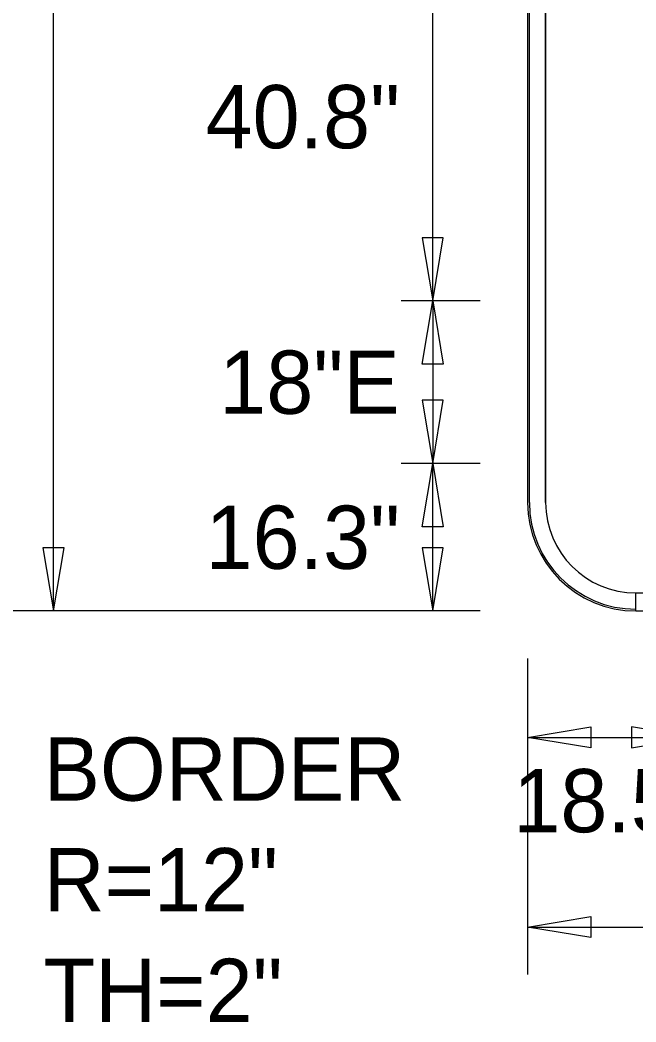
# Model space of a CAD drawing. Extents: x 2149934 to 2150188, y 145114 to 145238.
# Drawn here: x 2150026.84 to 2150032.52, y 145140.59 to 145149.83 of the extents above; entities that cross this region are included whole.
import ezdxf

# ---------------------------------------------------------------- set-up
doc = ezdxf.new("R2010")
doc.units = 0
for name, color, linetype in [('GSBWFILL', 7, 'Continuous'), ('GSCOLORFILL', 7, 'Continuous'), ('GSDIMS', 7, 'Continuous'), ('GSOUTLINE', 7, 'Continuous')]:
    doc.layers.add(name, color=color, linetype=linetype)

msp = doc.modelspace()

# ---------------------------------------------------------------- linework, layer by layer
at = {"layer": 'GSBWFILL'}
for p, q in [((2150031.5199, 145156.3826), (2150031.5199, 145145.3826)), ((2150031.6865, 145145.3826), (2150031.6865, 145156.3826)), ((2150032.5199, 145144.3826), (2150032.5199, 145144.5493))]:
    msp.add_line(p, q, dxfattribs=at)
for radius in [1, 0.8333]:
    msp.add_arc((2150032.5199, 145145.3826), radius, 180, 270, dxfattribs=at)
at = {"layer": 'GSCOLORFILL'}
for p, q in [((2150031.5199, 145156.3826), (2150031.5199, 145145.3826)), ((2150031.5199, 145156.3826), (2150031.5199, 145145.3826)), ((2150031.5199, 145156.3826), (2150031.5199, 145145.3826)), ((2150031.5365, 145145.3826), (2150031.5365, 145156.3826)), ((2150031.6865, 145145.3826), (2150031.6865, 145156.3826)), ((2150032.5199, 145144.3826), (2150032.5199, 145144.5493)), ((2150032.5199, 145144.3826), (2150032.5199, 145144.3993)), ((2150032.5199, 145144.3826), (2150046.0199, 145144.3826))]:
    msp.add_line(p, q, dxfattribs=at)
for radius in [1, 1, 1, 0.9833, 0.8333]:
    msp.add_arc((2150032.5199, 145145.3826), radius, 180, 270, dxfattribs=at)
at = {"layer": 'GSDIMS'}
for p, q in [((2150027.1448, 145144.3826), (2150027.1448, 145154.5852)), ((2150030.6448, 145147.2435), (2150030.6448, 145150.6434)), ((2150031.0823, 145147.2435), (2150030.3531, 145147.2435)), ((2150031.0823, 145147.2435), (2150030.3531, 145147.2435)), ((2150030.6448, 145147.2435), (2150030.6448, 145145.7435)), ((2150031.0823, 145145.7435), (2150030.3531, 145145.7435)), ((2150031.0823, 145145.7435), (2150030.3531, 145145.7435)), ((2150030.6448, 145144.3826), (2150030.6448, 145145.7435)), ((2150031.0823, 145144.3826), (2150024.0823, 145144.3826)), ((2150027.5823, 145144.3826), (2150026.8531, 145144.3826)), ((2150031.0823, 145144.3826), (2150030.3531, 145144.3826)), ((2150031.5198, 145143.9451), (2150031.5198, 145141.0284)), ((2150031.5198, 145143.6534), (2150031.5198, 145142.9243)), ((2150031.5198, 145143.2159), (2150033.0614, 145143.2159)), ((2150031.5198, 145141.9034), (2150031.5198, 145141.1743)), ((2150031.5198, 145141.4659), (2150047.0199, 145141.4659))]:
    msp.add_line(p, q, dxfattribs=at)
for points in [[(2150030.6448, 145147.2435), (2150030.742, 145147.8268), (2150030.5476, 145147.8268)], [(2150030.6448, 145147.2435), (2150030.742, 145146.6601), (2150030.5476, 145146.6601)], [(2150030.6448, 145145.7435), (2150030.742, 145146.3268), (2150030.5476, 145146.3268)], [(2150030.6448, 145145.7435), (2150030.742, 145145.1601), (2150030.5476, 145145.1601)], [(2150027.1448, 145144.3826), (2150027.242, 145144.9659), (2150027.0476, 145144.9659)], [(2150030.6448, 145144.3826), (2150030.742, 145144.9659), (2150030.5476, 145144.9659)], [(2150031.5198, 145143.2159), (2150032.1031, 145143.3132), (2150032.1031, 145143.1187)], [(2150033.0614, 145143.2159), (2150032.4781, 145143.3132), (2150032.4781, 145143.1187)], [(2150031.5198, 145141.4659), (2150032.1031, 145141.5632), (2150032.1031, 145141.3687)]]:
    msp.add_lwpolyline(points, close=True, dxfattribs=at)
at = {"layer": 'GSOUTLINE'}
for p, q in [((2150031.5199, 145156.3826), (2150031.5199, 145145.3826)), ((2150031.6865, 145156.3826), (2150031.6865, 145145.3826)), ((2150032.5199, 145144.5493), (2150046.0199, 145144.5493)), ((2150032.5199, 145144.3826), (2150046.0199, 145144.3826))]:
    msp.add_line(p, q, dxfattribs=at)
for radius in [1, 0.8333]:
    msp.add_arc((2150032.5199, 145145.3826), radius, 180, 270, dxfattribs=at)

# ---------------------------------------------------------------- texts
at = {"layer": 'GSDIMS'}
for s, p in [('40.8"', (2150028.5484, 145148.6517)), ('18"E', (2150028.6748, 145146.2018)), ('16.3"', (2150028.5484, 145144.7713)), ('BORDER', (2150027.0537, 145142.6326)), ('18.5"', (2150031.3883, 145142.3409)), ('R=12"', (2150027.0537, 145141.6118)), ('TH=2"', (2150027.0537, 145140.5909))]:
    msp.add_text(s, height=0.58333, dxfattribs=at).set_placement(p)

doc.saveas('drawing.dxf')
